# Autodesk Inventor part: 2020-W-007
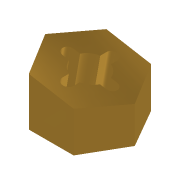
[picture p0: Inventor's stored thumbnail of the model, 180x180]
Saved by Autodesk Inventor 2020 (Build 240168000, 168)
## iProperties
Created: 2013-12
Part Number: 2020-W-007
Material: Mosiądz, miękki żółty
Document SubType Name: Modeling
Designer: F.Stasiak
Density: 8.47 g/cm^3
Appearance: Mosiądz — satynowy
Manager: www.cadconsulting.pl
Company: Fabian Stasiak CAD Consulting
Author: F.Stasiak
Subject: Zbiór ćwiczeń. Autodesk Inventor 2020. Kurs podstawowy
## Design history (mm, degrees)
sketch "Szkic1"
  geometry: L1 (10.104, 17.5)-(20.207, 0); L2 (20.207, 0)-(10.104, -17.5); L3 (10.104, -17.5)-(-10.104, -17.5); L4 (-10.104, -17.5)-(-20.207, 0); L5 (-20.207, 0)-(-10.104, 17.5); L6 (-10.104, 17.5)-(10.104, 17.5); 2 further points
  constraints: 12 end point, 1 coincident, 13 other
  dimensions: "d0" = 35 distance between parallel lines of L3 L6
extrude "Wyciągnięcie proste1" new body sketch "Szkic1" distance "d1" = 35; taper "d2" = 0 deg
node "Płaszczyzna konstrukcyjna1"
node "Płaszczyzna konstrukcyjna2"
  node "Oś konstrukcyjna1"
feature "Podział1"
sketch "Szkic2"
  geometry: L1 (0, 20.519)-(17.5, 10.259) reference; L2 (-17.5, 10.259)-(0, 20.519) reference; L3 (-17.5, -10.259)-(-17.5, 10.259) reference; L4 (0, -20.519)-(-17.5, -10.259) reference; L5 (17.5, -10.259)-(0, -20.519) reference; L6 (17.5, 10.259)-(17.5, -10.259) reference; L7 (-17.5, 0)-(17.5, 0); L8 (-10, 0)-(10, 0); L9 (-10, -2.5)-(10, -2.5); L10 (10, 2.5)-(-10, 2.5); L11 (0, -10)-(0, 10); L12 (2.5, -10)-(2.5, 10); L13 (-2.5, 10)-(-2.5, -10); C1 r 7.5 at (0, 0); A1 r 2.5 centre (-10, 0) between (-10, 2.5) and (-10, -2.5); A2 r 2.5 centre (10, 0) between (10, -2.5) and (10, 2.5); A3 r 2.5 centre (0, -10) between (-2.5, -10) and (2.5, -10); A4 r 2.5 centre (0, 10) between (2.5, 10) and (-2.5, 10); 1 further point
  constraints: 18 end point, 9 tangent, 8 point on circle, 5 centre point, 5 midpoint, 2 parallel, 1 perpendicular, 1 point on line
  dimensions: "d12" = 10 distance of C1.centre L8.end; "d13" = 5 diameter of A2; "d14" = 10 distance of C1.centre L11.end; "d15" = 5 diameter of A4; "d18" = 25 dimension on A3 A4 (derived); "d19" = 25 dimension on A2 A1 (derived)
extrude "Wyciągnięcie proste3" cut sketch "Szkic2" extent not by distance; stored distance "d16" = 30; taper "d17" = 0 deg
node "Bryła1"
node "Pętla rzutowana1"
other parameters: "d4" = 10 deg
